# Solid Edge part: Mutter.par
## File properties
Sűrűség: 0,000 kg/m^3
Pontosság: 0,990
Author: bmolnar
Last saved by: bmolnar
Revision: 76
Username: bmolnar
Dokumentum tartalom típus: 0
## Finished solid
Body 1: solid body, 23 faces, 46 edges, 24 vertices.
  Faces by surface: cone 14, plane 8, cylinder 1
  Edges by curve: spline 24, circle 16, line 6
Bounding box of the edges (mm): 7.000 x 21.939 x 19.000, from (0, -10.9697, -9.5) to (7, 10.9697, 9.5).
Cylindrical faces by radius (mm): R5.3235 x1
Conical faces (half-angle, radius in mm at the cone's reference point): 60 deg R5.6618 x2, 60 deg R10.2348 x12
Planar faces by outward normal: +x 1, +z 1, -x 1, -z 1, oblique 4
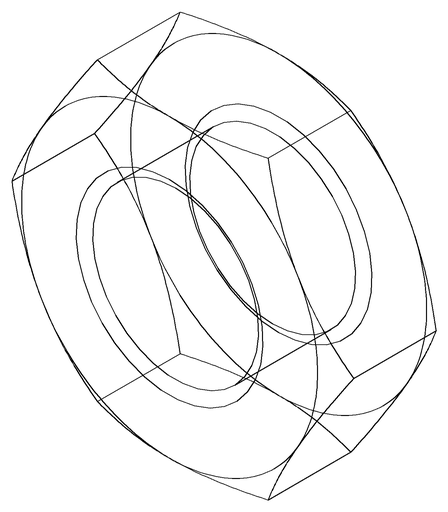
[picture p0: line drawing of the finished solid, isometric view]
